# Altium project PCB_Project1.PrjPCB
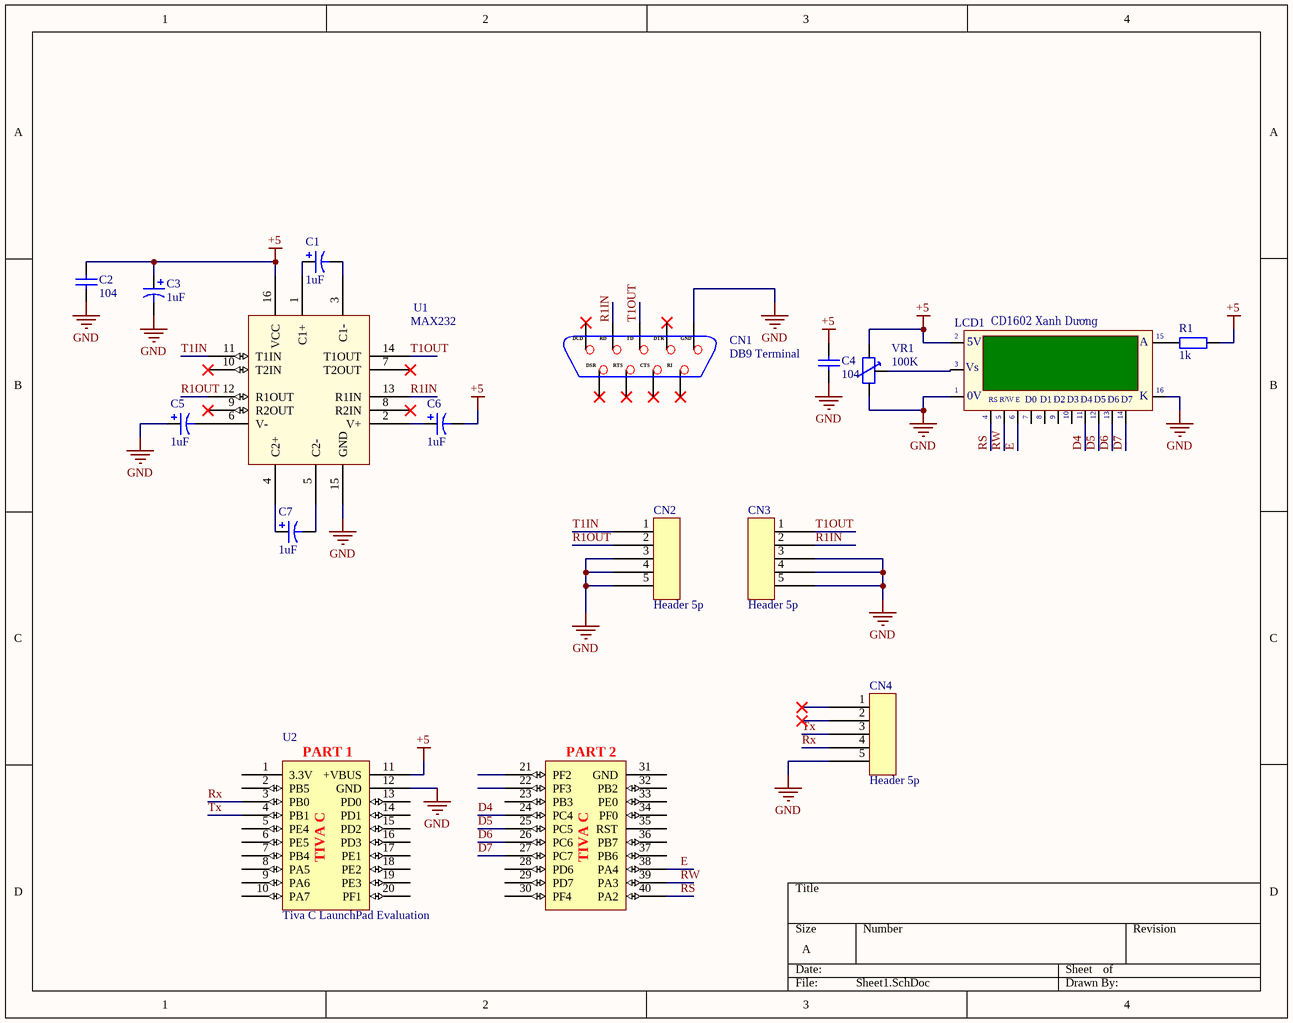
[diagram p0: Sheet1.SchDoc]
1 sheet, 16 parts. Net scope: global (net labels, ports and power ports of the same name join across sheets).
Board file: PCB1.PcbDoc

## Sheet Sheet1.SchDoc
size A

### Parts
C1  1uF  [TU HOA 3MM]
C2  104  [tu 0805]
C3  1uF  [TU HOA 3MM]
C4  104  [tu 0805]
C5  1uF  [TU HOA 3MM]
C6  1uF  [TU HOA 3MM]
C7  1uF  [TU HOA 3MM]
CN1  DB9 Terminal  [DB9]
CN2  Header 5p  [HEADER 5P MALE]
CN3  Header 5p  [HEADER 5P MALE]
CN4  Header 5p  [HEADER 5P MALE]
LCD1  CD1602 Xanh Dương  [LCD16X2]
R1  1k  [tro smd 0805]
U1  MAX232  [DIP16]
U2  Tiva C LaunchPad Evaluation  [Tiva C LaunchPad Kit]
VR1  100K  [VRES TOP]

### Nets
+5: C2.2 C3.1 C4.1 C6.2 LCD1.2(VDD) R1.2 U1.16(VCC) U2.11(+VBUS) VR1.1
GND: C2.1 C3.2 C4.2 C5.1 CN1.5(GND) CN2.3 CN2.4 CN2.5 CN3.3 CN3.4 CN3.5 CN4.5 LCD1.1(GND) LCD1.16(K) U1.15(GND) U2.12(GND) VR1.3
D4: LCD1.11(D4) U2.24(PC4)
D5: LCD1.12(D5) U2.25(PC5)
D6: LCD1.13(D6) U2.26(PC6)
D7: LCD1.14(D7) U2.27(PC7)
E: LCD1.6(~{EN}) U2.38(PA4)
R1IN: CN1.2(RD) CN3.2 U1.13(R1IN)
R1OUT: CN2.2 U1.12(R1OUT)
RS: LCD1.4(RS) U2.40(PA2)
RW: LCD1.5(R/~{W}) U2.39(PA3)
Rx: CN4.4 U2.3(PB0)
T1IN: CN2.1 U1.11(T1IN)
T1OUT: CN1.3(TD) CN3.1 U1.14(T1OUT)
Tx: CN4.3 U2.4(PB1)
NetC1_1: C1.1 U1.1(C1+)
NetC1_2: C1.2 U1.3(C1-)
NetC5_2: C5.2 U1.6(V-)
NetC6_1: C6.1 U1.2(V+)
NetC7_1: C7.1 U1.4(C2+)
NetC7_2: C7.2 U1.5(C2-)
NetLCD1_3: LCD1.3(VEE) VR1.2
NetLCD1_15: LCD1.15(A) R1.1

Not connected (* = marked no-connect by the designer): CN1 1(DCD)* 4(DTR)* 6(DSR)* 7(RTS)* 8(CTS)* 9(RI)*; CN4 1* 2*; LCD1 7(D0) 8(D1) 9(D2) 10(D3); U1 7(T2OUT)* 8(R2IN)* 9(R2OUT)* 10(T2IN)*; U2 1(3.3V) 2(PB5) 5(PE4) 6(PE5) 7(PB4) 8(PA5) 9(PA6) 10(PA7) 13(PD0) 14(PD1) 15(PD2) 16(PD3) 17(PE1) 18(PE2) 19(PE3) 20(PF1) 21(PF2) 22(PF3) 23(PB3) 28(PD6) 29(PD7) 30(PF4) 31(GND) 32(PB2) 33(PE0) 34(PF0) 35(RST) 36(PB7) 37(PB6)

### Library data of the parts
C1 C3 C5-C7 = Tu 3mm: Cắm
C2 C4 = Tu 0805 104 50V 10%: Dán; Don_Vi: Con; So_Chan: 2; Ten_Linh_Kien: Tụ 0805 104-100nF 10% 50V; Ma_Hang: MH004551
LCD1 = LCD16x2A: Cắm; Ten_Linh_Kien: CD1602 Xanh Dương ( Điện Áp 3.3V); Ma_Hang: MH002827; Don_Vi: Con
R1 = Tro 0805 1% 1k: Dán; Don_Vi: Con; So_Chan: 2; Ten_Linh_Kien: Trở 0805 1% 1k; Ma_Hang: MH005468
U2 = Tiva C LaunchPad Evaluation: Kit Tiva C LaunchPad Evaluation. Kit is using TM4C123GH6PM MCU
VR1 = Varrible Res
